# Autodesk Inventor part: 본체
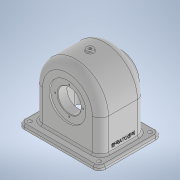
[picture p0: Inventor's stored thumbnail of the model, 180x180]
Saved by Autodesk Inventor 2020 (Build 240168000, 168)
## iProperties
Created: 2022-09
Part Number: 본체
Material: 일반
Document SubType Name: Modeling
Designer: Administrator
Density: 1 g/cm^3
Appearance: 기본값
Author: Administrator
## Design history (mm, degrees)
sketch "스케치1"
  geometry: L1 (-70, 54)-(70, 54); L2 (70, 54)-(70, -54); L3 (70, -54)-(-70, -54); L4 (-70, -54)-(-70, 54); L5 (-70, 54)-(70, -54); L6 (70, 54)-(-70, -54); 1 further point
  constraints: 12 end point, 2 midpoint, 2 parallel, 1 horizontal, 1 perpendicular
  dimensions: "d0" = 140 distance of L1.start L1.end; "d1" = 108 distance of L3.end L1.start
extrude "돌출1" new body sketch "스케치1" distance "d2" = 7; taper "d3" = 0 deg
fillet "모깎기1" dims "d4" = 10
sketch "스케치2"
  geometry: A1 r 10 centre (60, -44) between (60, -54) and (70, -44) reference; 2 further points
  constraints: 1 coincident
hole "구멍1" sketch "스케치2" at (60, -44) diameter "d5" = 6.6; stored, may be unused: countersink angle "d9" = 90 deg, drill point angle "d11" = 118 deg; dims "d6" = 11, "d7" = 4, "d8" = 2, "d10" = 13
sketch "스케치3"
  geometry: L1 (57, 64)-(57, 7); L2 (60, 7)-(70, 7) reference; L3 (-57, 64)-(-57, 7); L4 (-60, 0)-(60, 0) reference; L5 (57, 7)-(-57, 7); L6 (-56.7, 0)-(-56.7, 7) reference; A1 r 57 centre (0, 64) between (57, 64) and (-57, 64); 1 further point
  constraints: 6 end point, 2 point on circle, 2 tangent, 2 vertical, 1 centre point, 1 perpendicular, 1 point on line, 1 vertical alignment
  dimensions: "d16" = 114 diameter of A1; "d17" = 64 distance from line of L4 A1.centre
extrude "돌출2" new body sketch "스케치3" stored distance "d18" = 78; taper "d19" = 0 deg
fillet "모깎기2" dims "d20" = 14
feature "쉘1" dims "d21" = 5
sketch "스케치4"
  geometry: L1 (-52, -25)-(-52, 25) reference; L2 (-43, 34)-(43, 34) reference; L3 (52, 25)-(52, -25) reference; L4 (43, -34)-(-43, -34) reference; A1 r 9 centre (-43, 25) between (-43, 34) and (-52, 25) reference; A2 r 9 centre (43, 25) between (52, 25) and (43, 34) reference; A3 r 9 centre (43, -25) between (43, -34) and (52, -25) reference; A4 r 9 centre (-43, -25) between (-52, -25) and (-43, -34) reference; 1 further point
extrude "돌출3" cut sketch "스케치4" distance "d22" = 10; taper "d23" = 0 deg
feature "결합1"
  node "솔리드1"
sketch "스케치5"
  geometry: L1 (-39, 7)-(-39, 64) reference; L2 (-39, 64)-(67.883, 64); L3 (-20, 92)-(-20, 64); L4 (-25, 64)-(25, 64) reference; L5 (-20, 92)-(-34, 100.083); L6 (-34, 64)-(-34, 107) reference; L7 (-34, 0)-(-34, 64) reference; L8 (-34, 100.083)-(-34, 64); 2 further points
  constraints: 8 end point, 2 point on line, 1 horizontal, 1 perpendicular, 1 vertical
  dimensions: "d24" = 56 diameter of L3.start L2; "d25" = 60 deg angle of L3 L5; "d26" = 14 distance between parallel lines of L6 L3
revolve "회전1" sketch "스케치5" stored, may be unused: angle "d27" = 90 deg
sketch "스케치6"
  geometry: A1 r 43 centre (0, 64) between (43, 64) and (-43, 64) reference; 2 further points
  constraints: 1 coincident
hole "구멍2" sketch "스케치6" at (0, 64) diameter "d28" = 40; stored, may be unused: countersink angle "d32" = 90 deg, drill point angle "d34" = 0 deg; dims "d29" = 11, "d30" = 64, "d31" = 3, "d33" = 13
node "작업 평면1"
sketch "스케치7"
  geometry: C1 r 31 at (0, -64); A1 r 43 centre (0, -64) between (-43, -64) and (43, -64) reference; 1 further point
  constraints: 1 centre point, 1 coincident
  dimensions: "d36" = 62 diameter of C1
extrude "돌출4" join sketch "스케치7" stored distance "d37" = 10; taper "d38" = 0 deg
sketch "스케치8"
  geometry: C1 r 31 at (0, 0) reference; 2 further points
  constraints: 1 coincident
hole "구멍3" sketch "스케치8" at (0, 0) diameter "d39" = 35; stored, may be unused: countersink angle "d43" = 90 deg, drill point angle "d45" = 0 deg; dims "d40" = 11, "d41" = 40, "d42" = 16, "d44" = 13
node "작업 평면2"
sketch "스케치9"
  geometry: C1 r 6 at (-60, -54); 1 further point
  constraints: 1 centre point, 1 coincident
  dimensions: "d47" = 12 diameter of C1
extrude "돌출5" join sketch "스케치9" stored distance "d48" = 10; taper "d49" = 0 deg
sketch "스케치10"
  geometry: C1 r 6 at (0, 0) reference; 2 further points
  constraints: 1 coincident
hole "구멍4" sketch "스케치10" at (0, 0) diameter "d50" = 5.1881; stored, may be unused: countersink angle "d54" = 90 deg, drill point angle "d56" = 0 deg; dims "d51" = 12, "d52" = 40, "d53" = 16, "d55" = 16
fillet "모깎기3" dims "d57" = 1
sketch "스케치11"
  geometry: C1 r 32 at (0, 0) reference; 2 further points
  constraints: 1 vertical alignment
  dimensions: "d58" = 24 distance of C1.centre point (0, 24)
hole "구멍5" sketch "스케치11" at (0, 24) diameter "d59" = 2.459; stored, may be unused: countersink angle "d63" = 90 deg, drill point angle "d65" = 118 deg; dims "d60" = 7, "d61" = 40, "d62" = 16, "d64" = 9
sketch "스케치12"
  geometry: C1 r 20 at (0, 0) reference; 2 further points
  constraints: 1 vertical alignment
  dimensions: "d69" = 24 distance of C1.centre point (0, -24)
hole "구멍6" sketch "스케치12" at (0, -24) diameter "d70" = 2.459; stored, may be unused: countersink angle "d74" = 90 deg, drill point angle "d76" = 118 deg; dims "d71" = 7, "d72" = 40, "d73" = 16, "d75" = 9
node "작업 평면3"
sketch "스케치13"
  geometry: L1 (64, -19)-(64, -29) reference; L2 (0, -14)-(57, -14) reference; 2 further points
  constraints: 1 other
  dimensions: "d81" = 17 distance from line of point (47, 25) L1; "d82" = 39 distance from line of point (47, 25) L2
feature "엠보싱1" sketch "스케치13" dims "d0" = 140, "d1" = 108, "d83" = 0.5, "d84" = 0
fillet "모깎기4" dims "d85" = 0.6
chamfer "모따기1" distance "d86" = 1; stored, may be unused: second distance "d87" = 2, angle "d88" = 45 deg
fillet "모깎기5" dims "d89" = 3
pattern_linear "직사각형 패턴1"
pattern_circular "원형 패턴1" dims angle "d67" = 360 deg
pattern_circular "원형 패턴2" dims angle "d78" = 360 deg
node "솔리드2"
feature "A9D066F2-1C7D-4E18-AEED-F7BC21143FA4" dims "d5" = 6.6, "d6" = 11, "d7" = 4, "d8" = 2, "d9" = 90 deg, "d10" = 13, "d11" = 118 deg
other parameters: "d35" = 15, "d46" = -124
